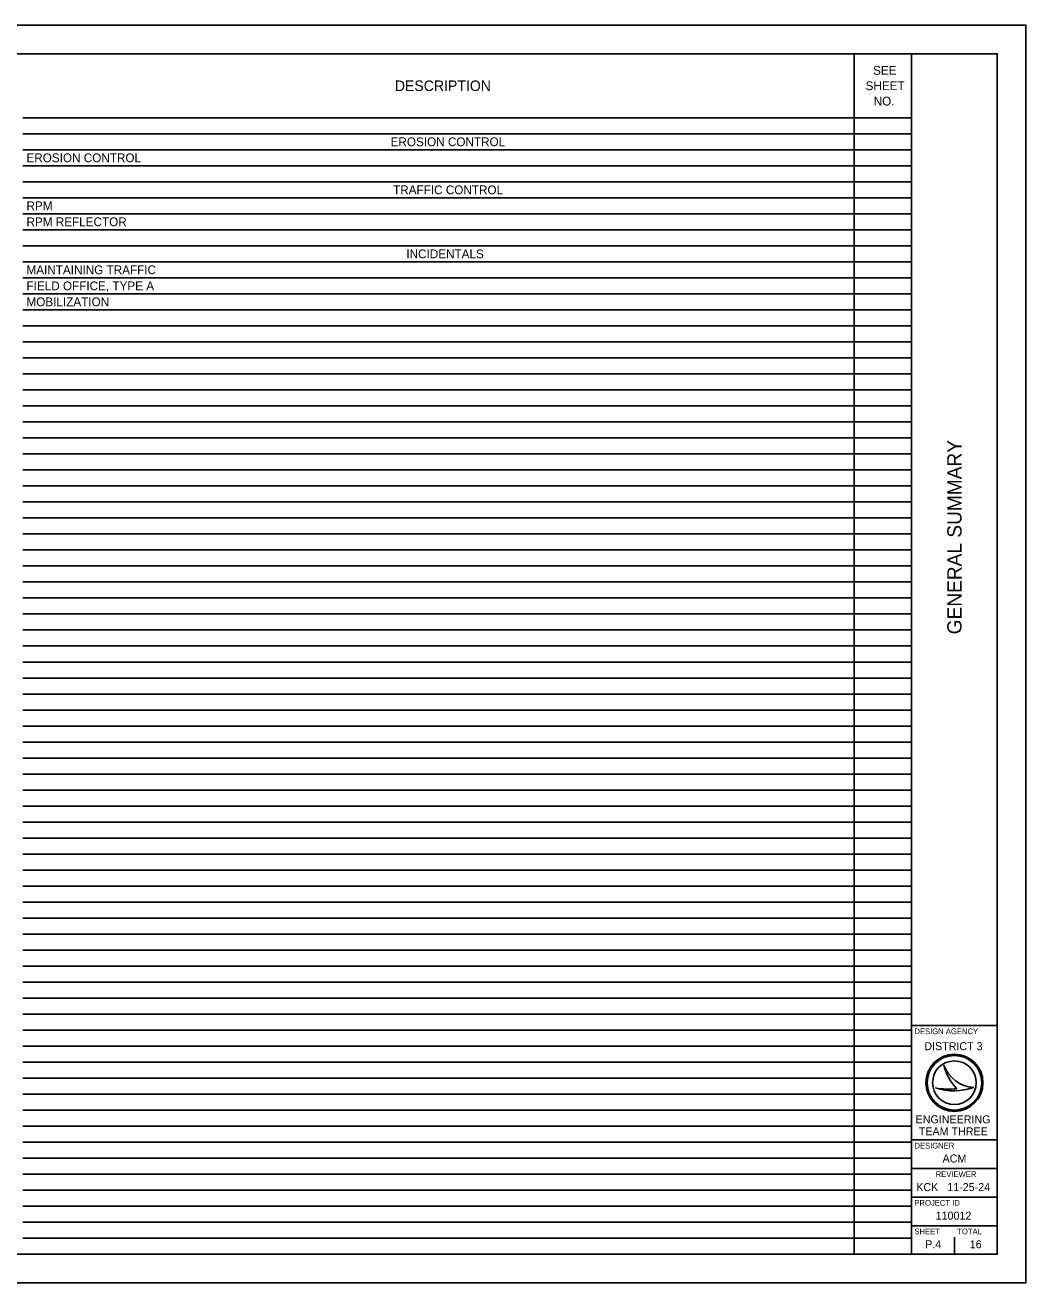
# Model space of a CAD drawing. Extents: x 0 to 34, y 0 to 22.
# Drawn here: x 16.49 to 34, y 0 to 22 of the extents above; entities that cross this region are included whole.
import ezdxf

# ---------------------------------------------------------------- set-up
doc = ezdxf.new("R2010")
doc.units = 0
for name, color, linetype in [('SH_Border', 7, 'Continuous'), ('SH_Cut_Line', 7, 'Continuous'), ('SH_Data', 7, 'Continuous'), ('SH_Text', 7, 'Continuous')]:
    doc.layers.add(name, color=color, linetype=linetype)

msp = doc.modelspace()

# ---------------------------------------------------------------- linework, layer by layer
at = {"layer": 'SH_Border'}
for p, q in [((32, 0.5), (32, 21.5)), ((32, 4.5), (33.5, 4.5)), ((32, 2.5), (33.5, 2.5)), ((32, 2), (33.5, 2)), ((32, 1.5), (33.5, 1.5)), ((32, 1), (33.5, 1))]:
    msp.add_line(p, q, dxfattribs=at)
msp.add_lwpolyline([(1.5, 21.5), (33.5, 21.5), (33.5, 0.5), (1.5, 0.5)], close=True, dxfattribs=at)
at = {"layer": 'SH_Cut_Line'}
msp.add_lwpolyline([(0, 0), (34, 0), (34, 22), (0, 22)], close=True, dxfattribs=at)
at = {"layer": 'SH_Data'}
for p, q in [((32.567, 3.81), (32.567, 3.81)), ((32.417, 3.41), (32.417, 3.41)), ((32.75, 3.5), (32.75, 3.5)), ((33.087, 3.419), (33.087, 3.419)), ((32.375, 0.675), (32.375, 0.675)), ((32.75, 0.5), (32.75, 0.8))]:
    msp.add_line(p, q, dxfattribs=at)
for radius in [0.5, 0.477, 0.477, 0.382]:
    msp.add_circle((32.75, 3.5), radius, dxfattribs=at)
for centre, radius, start, end in [((33.116, 3.998), 0.58, 198.9257, 198.9319), ((33.347, 3.97), 0.796, 191.6379, 191.6421), ((33.116, 3.998), 0.58, 198.9319, 267.1657), ((33.347, 3.97), 0.796, 191.6421, 226.0947), ((32.739, 4.37), 1.013, 251.4576, 290.0832), ((32.648, 4.654), 1.266, 259.4964, 259.4995), ((32.739, 4.37), 1.013, 251.4527, 251.4576), ((32.648, 4.654), 1.266, 259.4995, 276.6672)]:
    msp.add_arc(centre, radius, start, end, dxfattribs=at)
at = {"layer": 'SH_Text'}
for p, q in [((16.448, 21.5), (32, 21.5)), ((30.998, 21.5), (30.998, 21.22)), ((32, 21.5), (32, 21.22)), ((30.998, 21.22), (30.998, 20.94)), ((32, 21.22), (32, 20.94)), ((30.998, 20.94), (30.998, 20.66)), ((32, 20.94), (32, 20.66)), ((30.998, 20.66), (30.998, 20.38)), ((32, 20.66), (32, 20.38)), ((16.448, 20.38), (32, 20.38)), ((30.998, 20.38), (30.998, 20.1)), ((32, 20.38), (32, 20.1)), ((16.448, 20.1), (32, 20.1)), ((30.998, 20.1), (30.998, 18.7)), ((32, 20.1), (32, 18.7)), ((16.448, 19.82), (32, 19.82)), ((16.448, 19.54), (32, 19.54)), ((16.448, 19.26), (32, 19.26)), ((16.448, 18.98), (32, 18.98)), ((16.448, 18.7), (32, 18.7)), ((30.998, 18.7), (30.998, 18.14)), ((32, 18.7), (32, 18.14)), ((16.448, 18.42), (32, 18.42)), ((16.448, 18.14), (32, 18.14)), ((30.998, 18.14), (30.998, 17.86)), ((32, 18.14), (32, 17.86)), ((16.448, 17.86), (32, 17.86)), ((30.998, 17.86), (30.998, 17.58)), ((32, 17.86), (32, 17.58)), ((16.448, 17.58), (32, 17.58)), ((30.998, 17.58), (30.998, 17.3)), ((32, 17.58), (32, 17.3)), ((16.448, 17.3), (32, 17.3)), ((30.998, 17.3), (30.998, 17.02)), ((32, 17.3), (32, 17.02)), ((16.448, 17.02), (32, 17.02)), ((30.998, 17.02), (30.998, 16.74)), ((32, 17.02), (32, 16.74)), ((16.448, 16.74), (32, 16.74)), ((30.998, 16.74), (30.998, 16.18)), ((32, 16.74), (32, 16.18)), ((16.448, 16.46), (32, 16.46)), ((16.448, 16.18), (32, 16.18)), ((30.998, 16.18), (30.998, 15.9)), ((32, 16.18), (32, 15.9)), ((16.448, 15.9), (32, 15.9)), ((30.998, 15.9), (30.998, 15.62)), ((32, 15.9), (32, 15.62)), ((16.448, 15.62), (32, 15.62)), ((30.998, 15.62), (30.998, 15.34)), ((32, 15.62), (32, 15.34)), ((16.448, 15.34), (32, 15.34)), ((30.998, 15.34), (30.998, 14.78)), ((32, 15.34), (32, 14.78)), ((16.448, 15.06), (32, 15.06)), ((16.448, 14.78), (32, 14.78)), ((30.998, 14.78), (30.998, 14.5)), ((32, 14.78), (32, 14.5)), ((16.448, 14.5), (32, 14.5)), ((30.998, 14.5), (30.998, 14.22)), ((32, 14.5), (32, 14.22)), ((16.448, 14.22), (32, 14.22)), ((30.998, 14.22), (30.998, 13.94)), ((32, 14.22), (32, 13.94)), ((16.448, 13.94), (32, 13.94)), ((30.998, 13.94), (30.998, 11.7)), ((32, 13.94), (32, 11.7)), ((16.448, 13.66), (32, 13.66)), ((16.448, 13.38), (32, 13.38)), ((16.448, 13.1), (32, 13.1)), ((16.448, 12.82), (32, 12.82)), ((16.448, 12.54), (32, 12.54)), ((16.448, 12.26), (32, 12.26)), ((16.448, 11.98), (32, 11.98)), ((16.448, 11.7), (32, 11.7)), ((30.998, 11.7), (30.998, 11.42)), ((32, 11.7), (32, 11.42)), ((16.448, 11.42), (32, 11.42)), ((30.998, 11.42), (30.998, 10.3)), ((32, 11.42), (32, 10.3)), ((16.448, 11.14), (32, 11.14)), ((16.448, 10.86), (32, 10.86)), ((16.448, 10.58), (32, 10.58)), ((16.448, 10.3), (32, 10.3)), ((30.998, 10.3), (30.998, 10.02)), ((32, 10.3), (32, 10.02)), ((16.448, 10.02), (32, 10.02)), ((30.998, 10.02), (30.998, 9.74)), ((32, 10.02), (32, 9.74)), ((16.448, 9.74), (32, 9.74)), ((30.998, 9.74), (30.998, 8.9)), ((32, 9.74), (32, 8.9)), ((16.448, 9.46), (32, 9.46)), ((16.448, 9.18), (32, 9.18)), ((16.448, 8.9), (32, 8.9)), ((30.998, 8.9), (30.998, 8.34)), ((32, 8.9), (32, 8.34)), ((16.448, 8.62), (32, 8.62)), ((16.448, 8.34), (32, 8.34)), ((30.998, 8.34), (30.998, 7.5)), ((32, 8.34), (32, 7.5)), ((16.448, 8.06), (32, 8.06)), ((16.448, 7.78), (32, 7.78)), ((16.448, 7.5), (32, 7.5)), ((30.998, 7.5), (30.998, 6.94)), ((32, 7.5), (32, 6.94)), ((16.448, 7.22), (32, 7.22)), ((16.448, 6.94), (32, 6.94)), ((30.998, 6.94), (30.998, 6.1)), ((32, 6.94), (32, 6.1)), ((16.448, 6.66), (32, 6.66)), ((16.448, 6.38), (32, 6.38)), ((16.448, 6.1), (32, 6.1)), ((30.998, 6.1), (30.998, 4.98)), ((32, 6.1), (32, 4.98)), ((16.448, 5.82), (32, 5.82)), ((16.448, 5.54), (32, 5.54)), ((16.448, 5.26), (32, 5.26)), ((16.448, 4.98), (32, 4.98)), ((30.998, 4.98), (30.998, 4.7)), ((32, 4.98), (32, 4.7)), ((16.448, 4.7), (32, 4.7)), ((30.998, 4.7), (30.998, 3.58)), ((32, 4.7), (32, 3.58)), ((16.448, 4.42), (32, 4.42)), ((16.448, 4.14), (32, 4.14)), ((16.448, 3.86), (32, 3.86)), ((16.448, 3.58), (32, 3.58)), ((30.998, 3.58), (30.998, 3.3)), ((32, 3.58), (32, 3.3)), ((16.448, 3.3), (32, 3.3)), ((30.998, 3.3), (30.998, 2.18)), ((32, 3.3), (32, 2.18)), ((16.448, 3.02), (32, 3.02)), ((16.448, 2.74), (32, 2.74)), ((16.448, 2.46), (32, 2.46)), ((16.448, 2.18), (32, 2.18)), ((30.998, 2.18), (30.998, 1.9)), ((32, 2.18), (32, 1.9)), ((16.448, 1.9), (32, 1.9)), ((30.998, 1.9), (30.998, 0.78)), ((32, 1.9), (32, 0.78)), ((16.448, 1.62), (32, 1.62)), ((16.448, 1.34), (32, 1.34)), ((16.448, 1.06), (32, 1.06)), ((16.448, 0.78), (32, 0.78)), ((30.998, 0.78), (30.998, 0.5)), ((32, 0.78), (32, 0.5)), ((16.448, 0.5), (32, 0.5))]:
    msp.add_line(p, q, dxfattribs=at)

# ---------------------------------------------------------------- texts
at = {"layer": 'SH_Data'}
msp.add_text('GENERAL SUMMARY', height=0.25, rotation=90, dxfattribs=at).set_placement((32.875, 11.344))
for s, height, p in [('DESIGN AGENCY', 0.1, (32.05, 4.35)), ('DISTRICT 3', 0.14, (32.224, 4.07)), ('ENGINEERING', 0.14, (32.071, 2.79)), ('TEAM THREE', 0.14, (32.127, 2.58)), ('DESIGNER', 0.1, (32.05, 2.35)), ('ACM', 0.14, (32.543, 2.105)), ('REVIEWER', 0.1, (32.422, 1.85)), ('KCK', 0.14, (32.083, 1.605)), ('11-25-24', 0.14, (32.625, 1.605)), ('PROJECT ID', 0.1, (32.05, 1.35)), ('110012', 0.14, (32.421, 1.105)), ('SHEET', 0.1, (32.05, 0.85)), ('TOTAL', 0.1, (32.8, 0.85)), ('P.4', 0.14, (32.237, 0.605)), ('16', 0.14, (33.018, 0.605))]:
    msp.add_text(s, height=height, dxfattribs=at).set_placement(p)
at = {"layer": 'SH_Text'}
for s, height, p in [('SEE ', 0.1533, (31.326, 21.132)), ('DESCRIPTION', 0.184, (22.958, 20.848)), ('SHEET ', 0.1533, (31.196, 20.863)), ('NO.', 0.1533, (31.337, 20.595)), ('EROSION CONTROL', 0.15333, (22.884, 19.883)), ('EROSION CONTROL', 0.15333, (16.512, 19.603)), ('TRAFFIC CONTROL', 0.15333, (22.927, 19.043)), ('RPM', 0.1533, (16.512, 18.763)), ('RPM REFLECTOR', 0.15333, (16.512, 18.483)), ('INCIDENTALS', 0.15333, (23.159, 17.923)), ('MAINTAINING TRAFFIC', 0.15333, (16.512, 17.643)), ('FIELD OFFICE, TYPE A', 0.15333, (16.512, 17.363)), ('MOBILIZATION', 0.15333, (16.512, 17.083))]:
    msp.add_text(s, height=height, dxfattribs=at).set_placement(p)

doc.saveas('drawing.dxf')
